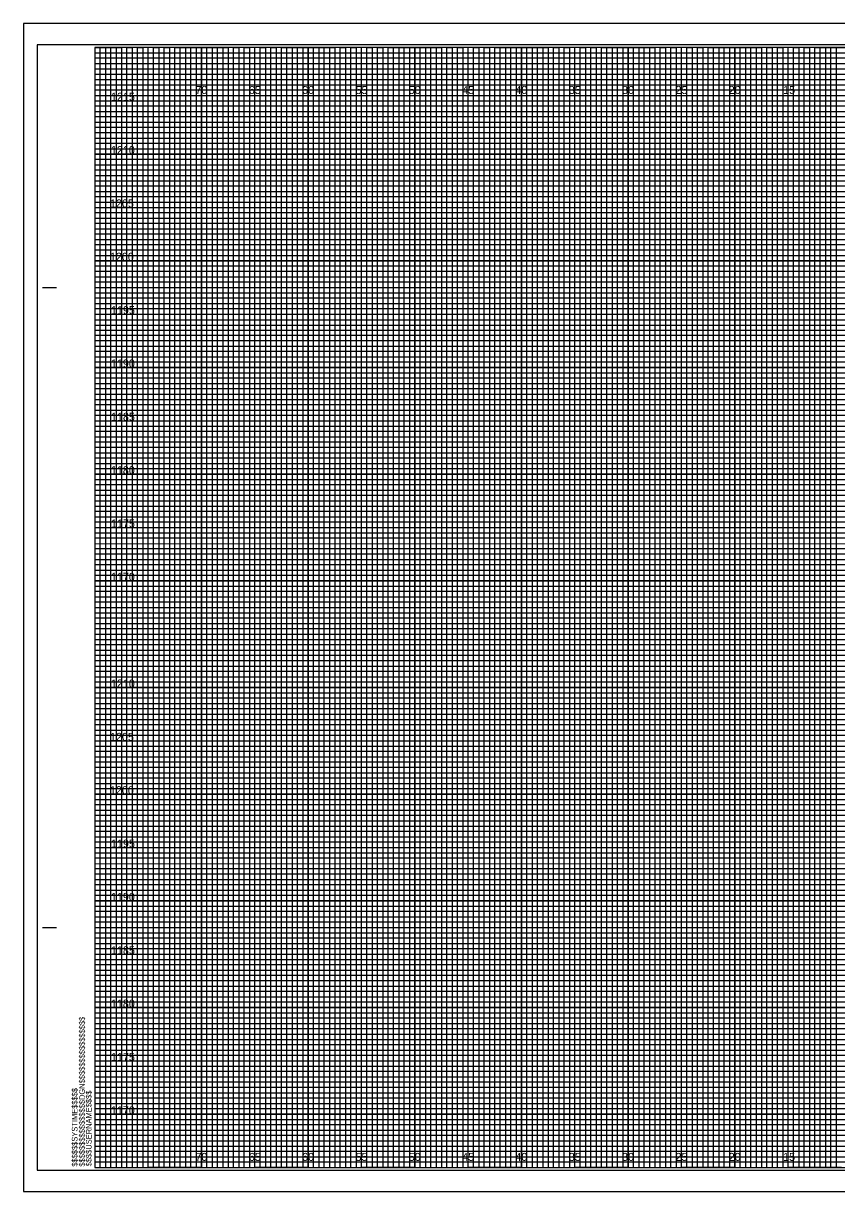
# Model space of a CAD drawing. Extents: x 3478 to 3647, y -9 to 1255.
# Drawn here: x 3478.3 to 3554.6, y 320.7 to 430.2 of the extents above; entities that cross this region are included whole.
import ezdxf

# ---------------------------------------------------------------- set-up
doc = ezdxf.new("R2010")
doc.units = 0
for name, color, linetype in [('Exist Cross Section Cell', 7, 'Continuous'), ('Prop CMT Subgrade Earthwork', 7, 'Continuous'), ('Prop Conc 4in Sidewalk', 7, 'Continuous'), ('Prop Conc Island Cover', 7, 'Continuous'), ('Sheet Cross Section CELL', 7, 'Continuous'), ('Sheet Cross Section Grid Minor 1 CELL', 7, 'Continuous'), ('Sheet Cross Section Grid Minor 2 CELL', 7, 'Continuous'), ('Sheet Cutting Line CELL', 7, 'Continuous'), ('Sheet DOT Grid CELL', 7, 'Continuous'), ('Sheet Plot Border Inside CELL', 7, 'Continuous')]:
    doc.layers.add(name, color=color, linetype=linetype)

msp = doc.modelspace()

# ---------------------------------------------------------------- linework, layer by layer
at = {"layer": 'Exist Cross Section Cell'}
for points in [[(3485.01, 427.97), (3487.51, 427.97), (3487.51, 322.97), (3492.51, 322.97), (3492.51, 427.97), (3497.51, 427.97), (3497.51, 322.97), (3502.51, 322.97), (3502.51, 427.97), (3507.51, 427.97), (3507.51, 322.97), (3512.51, 322.97), (3512.51, 427.97), (3517.51, 427.97), (3517.51, 322.97), (3522.51, 322.97), (3522.51, 427.97), (3527.51, 427.97), (3527.51, 322.97), (3532.51, 322.97), (3532.51, 427.97), (3537.51, 427.97), (3537.51, 322.97), (3542.51, 322.97), (3542.51, 427.97), (3547.51, 427.97), (3547.51, 322.97), (3552.51, 322.97), (3552.51, 427.97), (3557.51, 427.97)], [(3485.01, 425.47), (3622.51, 425.47)], [(3485.01, 415.47), (3645.01, 415.47), (3645.01, 420.47), (3485.01, 420.47)], [(3485.01, 405.47), (3645.01, 405.47), (3645.01, 410.47), (3485.01, 410.47)], [(3485.01, 395.47), (3645.01, 395.47), (3645.01, 400.47), (3485.01, 400.47)], [(3485.01, 385.47), (3645.01, 385.47), (3645.01, 390.47), (3485.01, 390.47)], [(3485.01, 375.47), (3645.01, 375.47), (3645.01, 380.47), (3485.01, 380.47)], [(3485.01, 365.47), (3645.01, 365.47), (3645.01, 370.47), (3485.01, 370.47)], [(3485.01, 355.47), (3645.01, 355.47), (3645.01, 360.47), (3485.01, 360.47)], [(3485.01, 345.47), (3645.01, 345.47), (3645.01, 350.47), (3485.01, 350.47)], [(3485.01, 335.47), (3645.01, 335.47), (3645.01, 340.47), (3485.01, 340.47)], [(3485.01, 325.47), (3645.01, 325.47), (3645.01, 330.47), (3485.01, 330.47)]]:
    msp.add_lwpolyline(points, dxfattribs=at)
at = {"layer": 'Prop CMT Subgrade Earthwork'}
msp.add_lwpolyline([(3478.31, 320.72), (3646.66, 320.72), (3646.66, 430.22), (3478.31, 430.22)], close=True, dxfattribs=at)
at = {"layer": 'Prop Conc 4in Sidewalk'}
for p, q in [((3490.01, 427.97), (3485.01, 427.97)), ((3490.01, 322.97), (3490.01, 427.97)), ((3500.01, 427.97), (3495.01, 427.97)), ((3495.01, 427.97), (3495.01, 322.97)), ((3500.01, 322.97), (3500.01, 427.97)), ((3510.01, 427.97), (3505.01, 427.97)), ((3505.01, 427.97), (3505.01, 322.97)), ((3510.01, 322.97), (3510.01, 427.97)), ((3520.01, 427.97), (3515.01, 427.97)), ((3515.01, 427.97), (3515.01, 322.97)), ((3520.01, 322.97), (3520.01, 427.97)), ((3530.01, 427.97), (3525.01, 427.97)), ((3525.01, 427.97), (3525.01, 322.97)), ((3530.01, 322.97), (3530.01, 427.97)), ((3540.01, 427.97), (3535.01, 427.97)), ((3535.01, 427.97), (3535.01, 322.97)), ((3540.01, 322.97), (3540.01, 427.97)), ((3550.01, 427.97), (3545.01, 427.97)), ((3545.01, 427.97), (3545.01, 322.97)), ((3550.01, 322.97), (3550.01, 427.97)), ((3495.01, 322.97), (3490.01, 322.97)), ((3505.01, 322.97), (3500.01, 322.97)), ((3515.01, 322.97), (3510.01, 322.97)), ((3525.01, 322.97), (3520.01, 322.97)), ((3535.01, 322.97), (3530.01, 322.97)), ((3545.01, 322.97), (3540.01, 322.97)), ((3555.01, 322.97), (3550.01, 322.97))]:
    msp.add_line(p, q, dxfattribs=at)
for points in [[(3485.01, 422.97), (3645.01, 422.97), (3645.01, 417.97), (3485.01, 417.97)], [(3485.01, 412.97), (3645.01, 412.97), (3645.01, 407.97), (3485.01, 407.97)], [(3485.01, 402.97), (3645.01, 402.97), (3645.01, 397.97), (3485.01, 397.97)], [(3485.01, 392.97), (3645.01, 392.97), (3645.01, 387.97), (3485.01, 387.97)], [(3485.01, 382.97), (3645.01, 382.97), (3645.01, 377.97), (3485.01, 377.97)], [(3485.01, 372.97), (3645.01, 372.97), (3645.01, 367.97), (3485.01, 367.97)], [(3485.01, 362.97), (3645.01, 362.97), (3645.01, 357.97), (3485.01, 357.97)], [(3485.01, 352.97), (3645.01, 352.97), (3645.01, 347.97), (3485.01, 347.97)], [(3485.01, 342.97), (3645.01, 342.97), (3645.01, 337.97), (3485.01, 337.97)], [(3485.01, 332.97), (3645.01, 332.97), (3645.01, 327.97), (3485.01, 327.97)]]:
    msp.add_lwpolyline(points, dxfattribs=at)
at = {"layer": 'Sheet Cross Section CELL'}
for p, q in [((3480.11, 405.47), (3481.36, 405.47)), ((3480.16, 405.47), (3481.41, 405.47)), ((3480.11, 345.47), (3481.36, 345.47)), ((3480.16, 345.47), (3481.41, 345.47))]:
    msp.add_line(p, q, dxfattribs=at)
msp.add_lwpolyline([(3645.01, 427.97), (3485.01, 427.97), (3485.01, 322.97), (3645.01, 322.97)], close=True, dxfattribs=at)
at = {"layer": 'Sheet Cross Section Grid Minor 1 CELL'}
for p, q in [((3485.01, 427.47), (3615.01, 427.47)), ((3615.01, 426.96), (3485.01, 426.96)), ((3485.01, 426.96), (3485.01, 426.47)), ((3485.01, 426.47), (3615.01, 426.47)), ((3615.01, 425.92), (3485.01, 425.92)), ((3485.01, 425.92), (3485.01, 424.97)), ((3485.01, 424.97), (3645.01, 424.97))]:
    msp.add_line(p, q, dxfattribs=at)
for points in [[(3485.01, 424.47), (3620.01, 424.47), (3645.01, 424.47), (3645.01, 423.97), (3485.01, 423.97)], [(3485.01, 423.47), (3645.01, 423.47), (3645.01, 422.47), (3485.01, 422.47)], [(3485.01, 421.97), (3645.01, 421.97), (3645.01, 421.47), (3485.01, 421.46)], [(3485.01, 420.97), (3645.01, 420.97), (3645.01, 419.97), (3485.01, 419.97)], [(3485.01, 419.47), (3645.01, 419.47), (3645.01, 418.97), (3485.01, 418.97)], [(3485.01, 418.47), (3645.01, 418.47), (3645.01, 417.47), (3485.01, 417.47)], [(3485.01, 416.97), (3645.01, 416.97), (3645.01, 416.47), (3485.01, 416.47)], [(3485.01, 415.97), (3645.01, 415.97), (3645.01, 414.97), (3485.01, 414.97)], [(3485.01, 414.47), (3645.01, 414.47), (3645.01, 413.97), (3485.01, 413.97)], [(3485.01, 413.47), (3645.01, 413.47), (3645.01, 412.47), (3485.01, 412.47)], [(3485.01, 411.97), (3645.01, 411.97), (3645.01, 411.47), (3485.01, 411.47)], [(3485.01, 410.97), (3645.01, 410.97), (3645.01, 409.95), (3645.01, 409.47), (3645.01, 408.97), (3485.01, 408.97)], [(3485.01, 409.97), (3645.01, 409.97), (3645.01, 409.47), (3485.01, 409.47)], [(3485.01, 408.47), (3645.01, 408.47), (3645.01, 407.47), (3485.01, 407.49)], [(3485.01, 407.49), (3645.01, 407.47), (3645.01, 406.97), (3485.01, 406.97)], [(3485.01, 406.47), (3645.01, 406.47), (3645.01, 405.97), (3485.01, 405.97)], [(3485.01, 404.97), (3645.01, 404.97), (3645.01, 404.47), (3485.01, 404.47)], [(3485.01, 403.97), (3645.01, 403.97), (3645.01, 403.47), (3485.01, 403.47)], [(3484.97, 402.42), (3645.01, 402.42), (3645.01, 401.91), (3484.97, 401.91)], [(3485.01, 401.47), (3645.01, 401.47), (3645.01, 400.97), (3485.01, 400.97)], [(3485.01, 399.97), (3645.01, 399.97), (3645.01, 399.47), (3485.01, 399.47)], [(3485.01, 398.97), (3645.01, 398.97), (3645.01, 398.47), (3485.01, 398.47)], [(3485.01, 397.47), (3645.01, 397.47), (3645.01, 396.97), (3485.01, 396.97)], [(3485.01, 396.47), (3645.01, 396.47), (3645.01, 395.97), (3485.01, 395.97)], [(3485.01, 394.97), (3645.01, 394.97), (3645.01, 394.47), (3485.01, 394.47)], [(3485.01, 393.97), (3645.01, 393.97), (3645.01, 393.47), (3485.01, 393.47)], [(3485.01, 392.47), (3645.01, 392.47), (3645, 391.96), (3485.01, 391.97)], [(3485.01, 391.47), (3645.01, 391.47), (3645.01, 390.97), (3485.01, 390.97)], [(3485.01, 389.97), (3645.01, 389.97), (3645.01, 389.47), (3485.01, 389.47)], [(3485.01, 388.97), (3645.01, 388.97), (3645.01, 388.47), (3485.01, 388.47)], [(3485.01, 387.47), (3645.01, 387.47), (3645.01, 386.97), (3485.01, 386.97)], [(3485.01, 386.47), (3645.01, 386.47), (3645.01, 385.97), (3485.01, 385.97)], [(3485.01, 384.97), (3645.01, 384.97), (3645.01, 384.47), (3485.01, 384.47)], [(3485.01, 383.97), (3645.01, 383.97), (3645.01, 383.47), (3485.01, 383.47)], [(3485.01, 382.47), (3645.01, 382.47), (3645.01, 381.97), (3485.01, 381.97)], [(3485.01, 381.47), (3645.04, 381.43), (3645.01, 380.97), (3485.01, 380.97)], [(3485.01, 379.97), (3645.01, 379.97), (3645.01, 379.47), (3485.01, 379.47)], [(3485.01, 378.97), (3645.01, 378.97), (3645.01, 378.47), (3485.01, 378.47)], [(3485.01, 377.47), (3645.01, 377.47), (3645.01, 376.97), (3485.01, 376.97)], [(3485.01, 376.47), (3645.01, 376.47), (3645.01, 375.97), (3485.01, 375.97)], [(3485.01, 374.97), (3645.01, 374.97), (3645.01, 374.47), (3485.01, 374.47)], [(3485.01, 373.97), (3645.01, 373.97), (3645.01, 373.47), (3485.01, 373.47)], [(3485.01, 372.47), (3645.01, 372.47), (3645.01, 371.97), (3485.01, 371.97)], [(3485.01, 371.47), (3645.01, 371.47), (3645.01, 370.97), (3485.01, 370.97)], [(3485.01, 369.97), (3645.01, 369.97), (3645.01, 369.47), (3485.01, 369.47)], [(3485.01, 368.97), (3645.01, 368.97), (3645.01, 368.47), (3485.01, 368.47)], [(3485.01, 367.47), (3645.01, 367.47), (3645.01, 366.97), (3485.01, 366.97)], [(3485.01, 366.47), (3645.01, 366.47), (3645.01, 365.97), (3485.01, 365.97)], [(3485.01, 364.97), (3645.01, 364.97), (3645.01, 364.47), (3485.01, 364.47)], [(3485.01, 363.97), (3645.01, 363.97), (3645.01, 363.47), (3485.01, 363.47)], [(3485.01, 362.47), (3645.01, 362.47), (3645, 361.96), (3485.01, 361.97)], [(3485.01, 361.47), (3645.01, 361.47), (3645.01, 360.97), (3485.01, 360.97)], [(3485.01, 359.97), (3645.01, 359.97), (3645.01, 359.47), (3485.01, 359.47)], [(3485.01, 358.97), (3645.01, 358.97), (3645.01, 358.47), (3485.01, 358.47)], [(3485.01, 357.47), (3645.01, 357.47), (3645.01, 356.97), (3485.01, 356.97)], [(3485.01, 356.47), (3645.01, 356.47), (3645.01, 355.97), (3485.01, 355.97)], [(3485.01, 354.97), (3645.01, 354.97), (3645.01, 354.47), (3485.01, 354.47)], [(3485.01, 353.97), (3645.01, 353.97), (3645.01, 353.47), (3485.01, 353.47)], [(3485.01, 352.47), (3645.01, 352.47), (3645.01, 351.97), (3485.01, 351.97)], [(3485.01, 351.47), (3645.04, 351.43), (3645.01, 350.97), (3485.01, 350.97)], [(3485.01, 349.97), (3645.01, 349.97), (3645.01, 349.47), (3485.01, 349.47)], [(3485.01, 348.97), (3645.01, 348.97), (3645.01, 348.47), (3485.01, 348.47)], [(3485.01, 347.47), (3645.01, 347.47), (3645.01, 346.97), (3485.01, 346.97)], [(3485.01, 346.47), (3645.01, 346.47), (3645.01, 345.97), (3485.01, 345.97)], [(3485.01, 344.97), (3645.01, 344.97), (3645.01, 344.47), (3485.01, 344.47)], [(3485.01, 343.97), (3645.01, 343.97), (3645.01, 343.47), (3485.01, 343.47)], [(3485.01, 342.47), (3645.01, 342.47), (3645.01, 341.97), (3485.01, 341.97)], [(3485.01, 341.47), (3645.01, 341.47), (3645.01, 340.97), (3485.01, 340.97)], [(3485.01, 339.97), (3645.01, 339.97), (3645.01, 339.47), (3485.01, 339.47)], [(3485.01, 338.97), (3645.01, 338.97), (3645.01, 338.47), (3485.01, 338.47)], [(3485.01, 337.47), (3645.01, 337.47), (3645.01, 336.97), (3485.01, 336.97)], [(3485.01, 336.47), (3645.01, 336.47), (3645.01, 335.97), (3485.01, 335.97)], [(3485.01, 334.97), (3645.01, 334.97), (3645.01, 334.47), (3485.01, 334.47)], [(3485.01, 333.97), (3645.01, 333.97), (3645.01, 333.47), (3485.01, 333.47)], [(3485.01, 332.47), (3645.01, 332.47), (3645.01, 331.97), (3485.01, 331.97)], [(3485.01, 331.47), (3645.01, 331.47), (3645.01, 330.97), (3485.01, 330.97)], [(3485.01, 329.97), (3645.01, 329.97), (3645.01, 329.47), (3485.01, 329.47)], [(3485.01, 328.97), (3645.01, 328.97), (3645.01, 328.47), (3485.01, 328.47)], [(3485.01, 327.47), (3645.01, 327.47), (3645.01, 326.97), (3485.01, 326.97)], [(3485.01, 326.47), (3645.01, 326.47), (3645.01, 325.97), (3485.01, 325.97)], [(3485.01, 324.97), (3645.01, 324.97), (3645.01, 324.47), (3485.01, 324.47)], [(3485.01, 323.97), (3645.01, 323.97), (3645.01, 323.47), (3485.01, 323.47)]]:
    msp.add_lwpolyline(points, dxfattribs=at)
at = {"layer": 'Sheet Cross Section Grid Minor 2 CELL'}
for points in [[(3485.01, 322.97), (3485.51, 322.97), (3485.51, 427.97), (3486.01, 427.97), (3486.01, 322.97)], [(3486.01, 322.97), (3486.51, 322.97), (3486.51, 427.97), (3487.01, 427.97), (3487.01, 322.97)], [(3487.51, 322.97), (3488.01, 322.97), (3488.01, 427.97), (3488.51, 427.97), (3488.51, 322.97)], [(3488.51, 322.97), (3489.01, 322.97), (3489.01, 427.97), (3489.51, 427.97), (3489.51, 322.97)], [(3490.01, 322.97), (3490.51, 322.97), (3490.51, 427.97), (3491.01, 427.97), (3491.01, 322.97)], [(3491.01, 322.97), (3491.51, 322.97), (3491.51, 427.97), (3492.01, 427.97), (3492.01, 322.97)], [(3492.51, 322.97), (3493.01, 322.97), (3493.01, 427.97), (3493.51, 427.97), (3493.51, 322.97)], [(3493.51, 322.97), (3494.01, 322.97), (3494.01, 427.97), (3494.51, 427.97), (3494.51, 322.97)], [(3495.01, 322.97), (3495.51, 322.97), (3495.51, 427.97), (3496.01, 427.97), (3496.01, 322.97)], [(3496.01, 322.97), (3496.51, 322.97), (3496.51, 427.97), (3497.01, 427.97), (3497.01, 322.97)], [(3497.51, 322.97), (3498.01, 322.97), (3498.01, 427.97), (3498.51, 427.97), (3498.51, 322.97)], [(3498.51, 322.97), (3499.01, 322.97), (3499.01, 427.97), (3499.51, 427.97), (3499.51, 322.97)], [(3500.01, 322.97), (3500.51, 322.97), (3500.51, 427.97), (3501.01, 427.97), (3501.01, 322.97)], [(3501.01, 322.97), (3501.51, 322.97), (3501.51, 427.97), (3502.01, 427.97), (3502.01, 322.97)], [(3502.51, 322.97), (3503.01, 322.97), (3503.01, 427.97), (3503.51, 427.97), (3503.51, 322.97)], [(3503.51, 322.97), (3504.01, 322.97), (3504.01, 427.97), (3504.51, 427.97), (3504.51, 322.97)], [(3505.01, 322.97), (3505.51, 322.97), (3505.51, 427.97), (3506.01, 427.97), (3506.01, 322.97)], [(3506.01, 322.97), (3506.51, 322.97), (3506.51, 427.97), (3507.01, 427.97), (3507.01, 322.97)], [(3507.51, 322.97), (3508.01, 322.97), (3508.01, 427.97), (3508.51, 427.97), (3508.51, 322.97)], [(3508.51, 322.97), (3509.01, 322.97), (3509.01, 427.97), (3509.51, 427.97), (3509.51, 322.97)], [(3510.01, 322.97), (3510.51, 322.97), (3510.51, 427.97), (3511.01, 427.97), (3511.01, 322.97)], [(3511.01, 322.97), (3511.51, 322.97), (3511.51, 427.97), (3512.01, 427.97), (3512.01, 322.97)], [(3512.51, 322.97), (3513.01, 322.97), (3513.01, 427.97), (3513.51, 427.97), (3513.51, 322.97)], [(3513.51, 322.97), (3514.01, 322.97), (3514.01, 427.97), (3514.51, 427.97), (3514.51, 322.97)], [(3515.01, 322.97), (3515.51, 322.97), (3515.51, 427.97), (3516.01, 427.97), (3516.01, 322.97)], [(3516.01, 322.97), (3516.51, 322.97), (3516.51, 427.97), (3517.01, 427.97), (3517.01, 322.97)], [(3517.51, 322.97), (3518.01, 322.97), (3518.01, 427.97), (3518.51, 427.97), (3518.51, 322.97)], [(3518.51, 322.97), (3519.01, 322.97), (3519.01, 427.97), (3519.51, 427.97), (3519.51, 322.97)], [(3520.01, 322.97), (3520.51, 322.97), (3520.51, 427.97), (3521.01, 427.97), (3521.01, 322.97)], [(3521.01, 322.97), (3521.51, 322.97), (3521.51, 427.97), (3522.01, 427.97), (3522.01, 322.97)], [(3522.51, 322.97), (3523.01, 322.97), (3523.01, 427.97), (3523.51, 427.97), (3523.51, 322.97)], [(3523.51, 322.97), (3524.01, 322.97), (3524.01, 427.97), (3524.51, 427.97), (3524.51, 322.97)], [(3525.01, 322.97), (3525.51, 322.97), (3525.51, 427.97), (3526.01, 427.97), (3526.01, 322.97)], [(3526.01, 322.97), (3526.51, 322.97), (3526.51, 427.97), (3527.01, 427.97), (3527.01, 322.97)], [(3527.51, 322.97), (3528.01, 322.97), (3528.01, 427.97), (3528.51, 427.97), (3528.51, 322.97)], [(3528.51, 322.97), (3529.01, 322.97), (3529.01, 427.97), (3529.51, 427.97), (3529.51, 322.97)], [(3530.01, 322.97), (3530.51, 322.97), (3530.51, 427.97), (3531.01, 427.97), (3531.01, 322.97)], [(3531.01, 322.97), (3531.51, 322.97), (3531.51, 427.97), (3532.01, 427.97), (3532.01, 322.97)], [(3532.51, 322.97), (3533.01, 322.97), (3533.01, 427.97), (3533.51, 427.97), (3533.51, 322.97)], [(3533.51, 322.97), (3534.01, 322.97), (3534.01, 427.97), (3534.51, 427.97), (3534.51, 322.97)], [(3535.01, 322.97), (3535.51, 322.97), (3535.51, 427.97), (3536.01, 427.97), (3536.01, 322.97)], [(3536.01, 322.97), (3536.51, 322.97), (3536.51, 427.97), (3537.01, 427.97), (3537.01, 322.97)], [(3537.51, 322.97), (3538.01, 322.97), (3538.01, 427.97), (3538.51, 427.97), (3538.51, 322.97)], [(3538.51, 322.97), (3539.01, 322.97), (3539.01, 427.97), (3539.51, 427.97), (3539.51, 322.97)], [(3540.01, 322.97), (3540.51, 322.97), (3540.51, 427.97), (3541.01, 427.97), (3541.01, 322.97)], [(3541.01, 322.97), (3541.51, 322.97), (3541.51, 427.97), (3542.01, 427.97), (3542.01, 322.97)], [(3542.51, 322.97), (3543.01, 322.97), (3543.01, 427.97), (3543.51, 427.97), (3543.51, 322.97)], [(3543.51, 322.97), (3544.01, 322.97), (3544.01, 427.97), (3544.51, 427.97), (3544.51, 322.97)], [(3545.01, 322.97), (3545.51, 322.97), (3545.51, 427.97), (3546.01, 427.97), (3546.01, 322.97)], [(3546.01, 322.97), (3546.51, 322.97), (3546.51, 427.97), (3547.01, 427.97), (3547.01, 322.97)], [(3547.51, 322.97), (3548.01, 322.97), (3548.01, 427.97), (3548.51, 427.97), (3548.51, 322.97)], [(3548.51, 322.97), (3549.01, 322.97), (3549.01, 427.97), (3549.51, 427.97), (3549.51, 322.97)], [(3550.01, 322.97), (3550.51, 322.97), (3550.51, 427.97), (3551.01, 427.97), (3551.01, 322.97)], [(3551.01, 322.97), (3551.51, 322.97), (3551.51, 427.97), (3552.01, 427.97), (3552.01, 322.97)], [(3552.51, 322.97), (3553.01, 322.97), (3553.01, 427.97), (3553.51, 427.97), (3553.51, 322.97)], [(3553.51, 322.97), (3554.01, 322.97), (3554.01, 427.97), (3554.51, 427.97), (3554.51, 322.97)]]:
    msp.add_lwpolyline(points, dxfattribs=at)
at = {"layer": 'Sheet Cutting Line CELL'}
for p, q in [((3646.66, 430.22), (3478.31, 430.22)), ((3478.31, 430.22), (3478.31, 320.72)), ((3478.31, 320.72), (3646.66, 320.72))]:
    msp.add_line(p, q, dxfattribs=at)
at = {"layer": 'Sheet DOT Grid CELL'}
for p, q in [((3490.01, 322.97), (3490.01, 427.97)), ((3495.01, 322.97), (3495.01, 427.97)), ((3500.01, 322.97), (3500.01, 427.97)), ((3505.01, 322.97), (3505.01, 427.97)), ((3510.01, 322.97), (3510.01, 427.97)), ((3515.01, 322.97), (3515.01, 427.97)), ((3520.01, 322.97), (3520.01, 427.97)), ((3525.01, 322.97), (3525.01, 427.97)), ((3530.01, 322.97), (3530.01, 427.97)), ((3535.01, 322.97), (3535.01, 427.97)), ((3540.01, 322.97), (3540.01, 427.97)), ((3545.01, 322.97), (3545.01, 427.97)), ((3550.01, 322.97), (3550.01, 427.97)), ((3485.01, 422.97), (3645.01, 422.97)), ((3485.01, 417.97), (3645.01, 417.97)), ((3485.01, 412.97), (3645.01, 412.97)), ((3485.01, 407.97), (3645.01, 407.97)), ((3485.01, 402.97), (3645.01, 402.97)), ((3485.01, 397.97), (3645.01, 397.97)), ((3485.01, 392.97), (3645.01, 392.97)), ((3485.01, 387.97), (3645.01, 387.97)), ((3485.01, 382.97), (3645.01, 382.97)), ((3485.01, 377.97), (3645.01, 377.97)), ((3485.01, 372.97), (3645.01, 372.97)), ((3485.01, 367.97), (3645.01, 367.97)), ((3485.01, 362.97), (3645.01, 362.97)), ((3485.01, 357.97), (3645.01, 357.97)), ((3485.01, 352.97), (3645.01, 352.97)), ((3485.01, 347.97), (3645.01, 347.97)), ((3485.01, 342.97), (3645.01, 342.97)), ((3485.01, 337.97), (3645.01, 337.97)), ((3485.01, 332.97), (3645.01, 332.97)), ((3485.01, 327.97), (3645.01, 327.97))]:
    msp.add_line(p, q, dxfattribs=at)
at = {"layer": 'Sheet Plot Border Inside CELL'}
msp.add_lwpolyline([(3479.61, 322.72), (3646.21, 322.72), (3646.21, 428.22), (3479.61, 428.22)], close=True, dxfattribs=at)

# ---------------------------------------------------------------- texts
at = {"layer": 'Prop Conc Island Cover'}
for s, p in [('70', (3494.44, 423.6)), ('65', (3499.45, 423.6)), ('60', (3504.44, 423.6)), ('55', (3509.45, 423.6)), ('50', (3514.44, 423.6)), ('45', (3519.45, 423.6)), ('40', (3524.44, 423.6)), ('35', (3529.45, 423.6)), ('30', (3534.44, 423.6)), ('25', (3539.45, 423.6)), ('20', (3544.44, 423.6)), ('15', (3549.54, 423.6)), ('1215', (3486.53, 422.97)), ('1210', (3486.52, 417.97)), ('1205', (3486.44, 412.97)), ('1200', (3486.43, 407.97)), ('1195', (3486.53, 402.97)), ('1190', (3486.52, 397.97)), ('1185', (3486.53, 392.97)), ('1180', (3486.52, 387.97)), ('1175', (3486.53, 382.97)), ('1170', (3486.52, 377.97)), ('1210', (3486.52, 367.97)), ('1205', (3486.44, 362.97)), ('1200', (3486.43, 357.97)), ('1195', (3486.53, 352.97)), ('1190', (3486.52, 347.97)), ('1185', (3486.53, 342.97)), ('1180', (3486.52, 337.97)), ('1175', (3486.53, 332.97)), ('1170', (3486.52, 327.97)), ('70', (3494.44, 323.6)), ('65', (3499.45, 323.6)), ('60', (3504.44, 323.6)), ('55', (3509.45, 323.6)), ('50', (3514.44, 323.6)), ('45', (3519.45, 323.6)), ('40', (3524.44, 323.6)), ('35', (3529.45, 323.6)), ('30', (3534.44, 323.6)), ('25', (3539.45, 323.6)), ('20', (3544.44, 323.6)), ('15', (3549.54, 323.6))]:
    msp.add_text(s, height=0.75, dxfattribs=at).set_placement(p)
at = {"layer": 'Sheet Cross Section CELL'}
for s, p in [('$$$$$$$$$$$$$$$$DGN$$$$$$$$$$$$$$$$', (3484.07, 323.06)), ('$$$$$$SYSTIME$$$$$', (3483.38, 323.06)), ('$$$$USERNAME$$$$', (3484.7, 323.09))]:
    msp.add_text(s, height=0.525, rotation=90, dxfattribs=at).set_placement(p)

doc.saveas('drawing.dxf')
